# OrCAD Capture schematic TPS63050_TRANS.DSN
size D; title: TPS63050, Single Inductor Buck-Boost With 1-A Switches and; note: Datasheet: SLVSAM8D  EVM: SLVU806; note: Step-Down Converter.
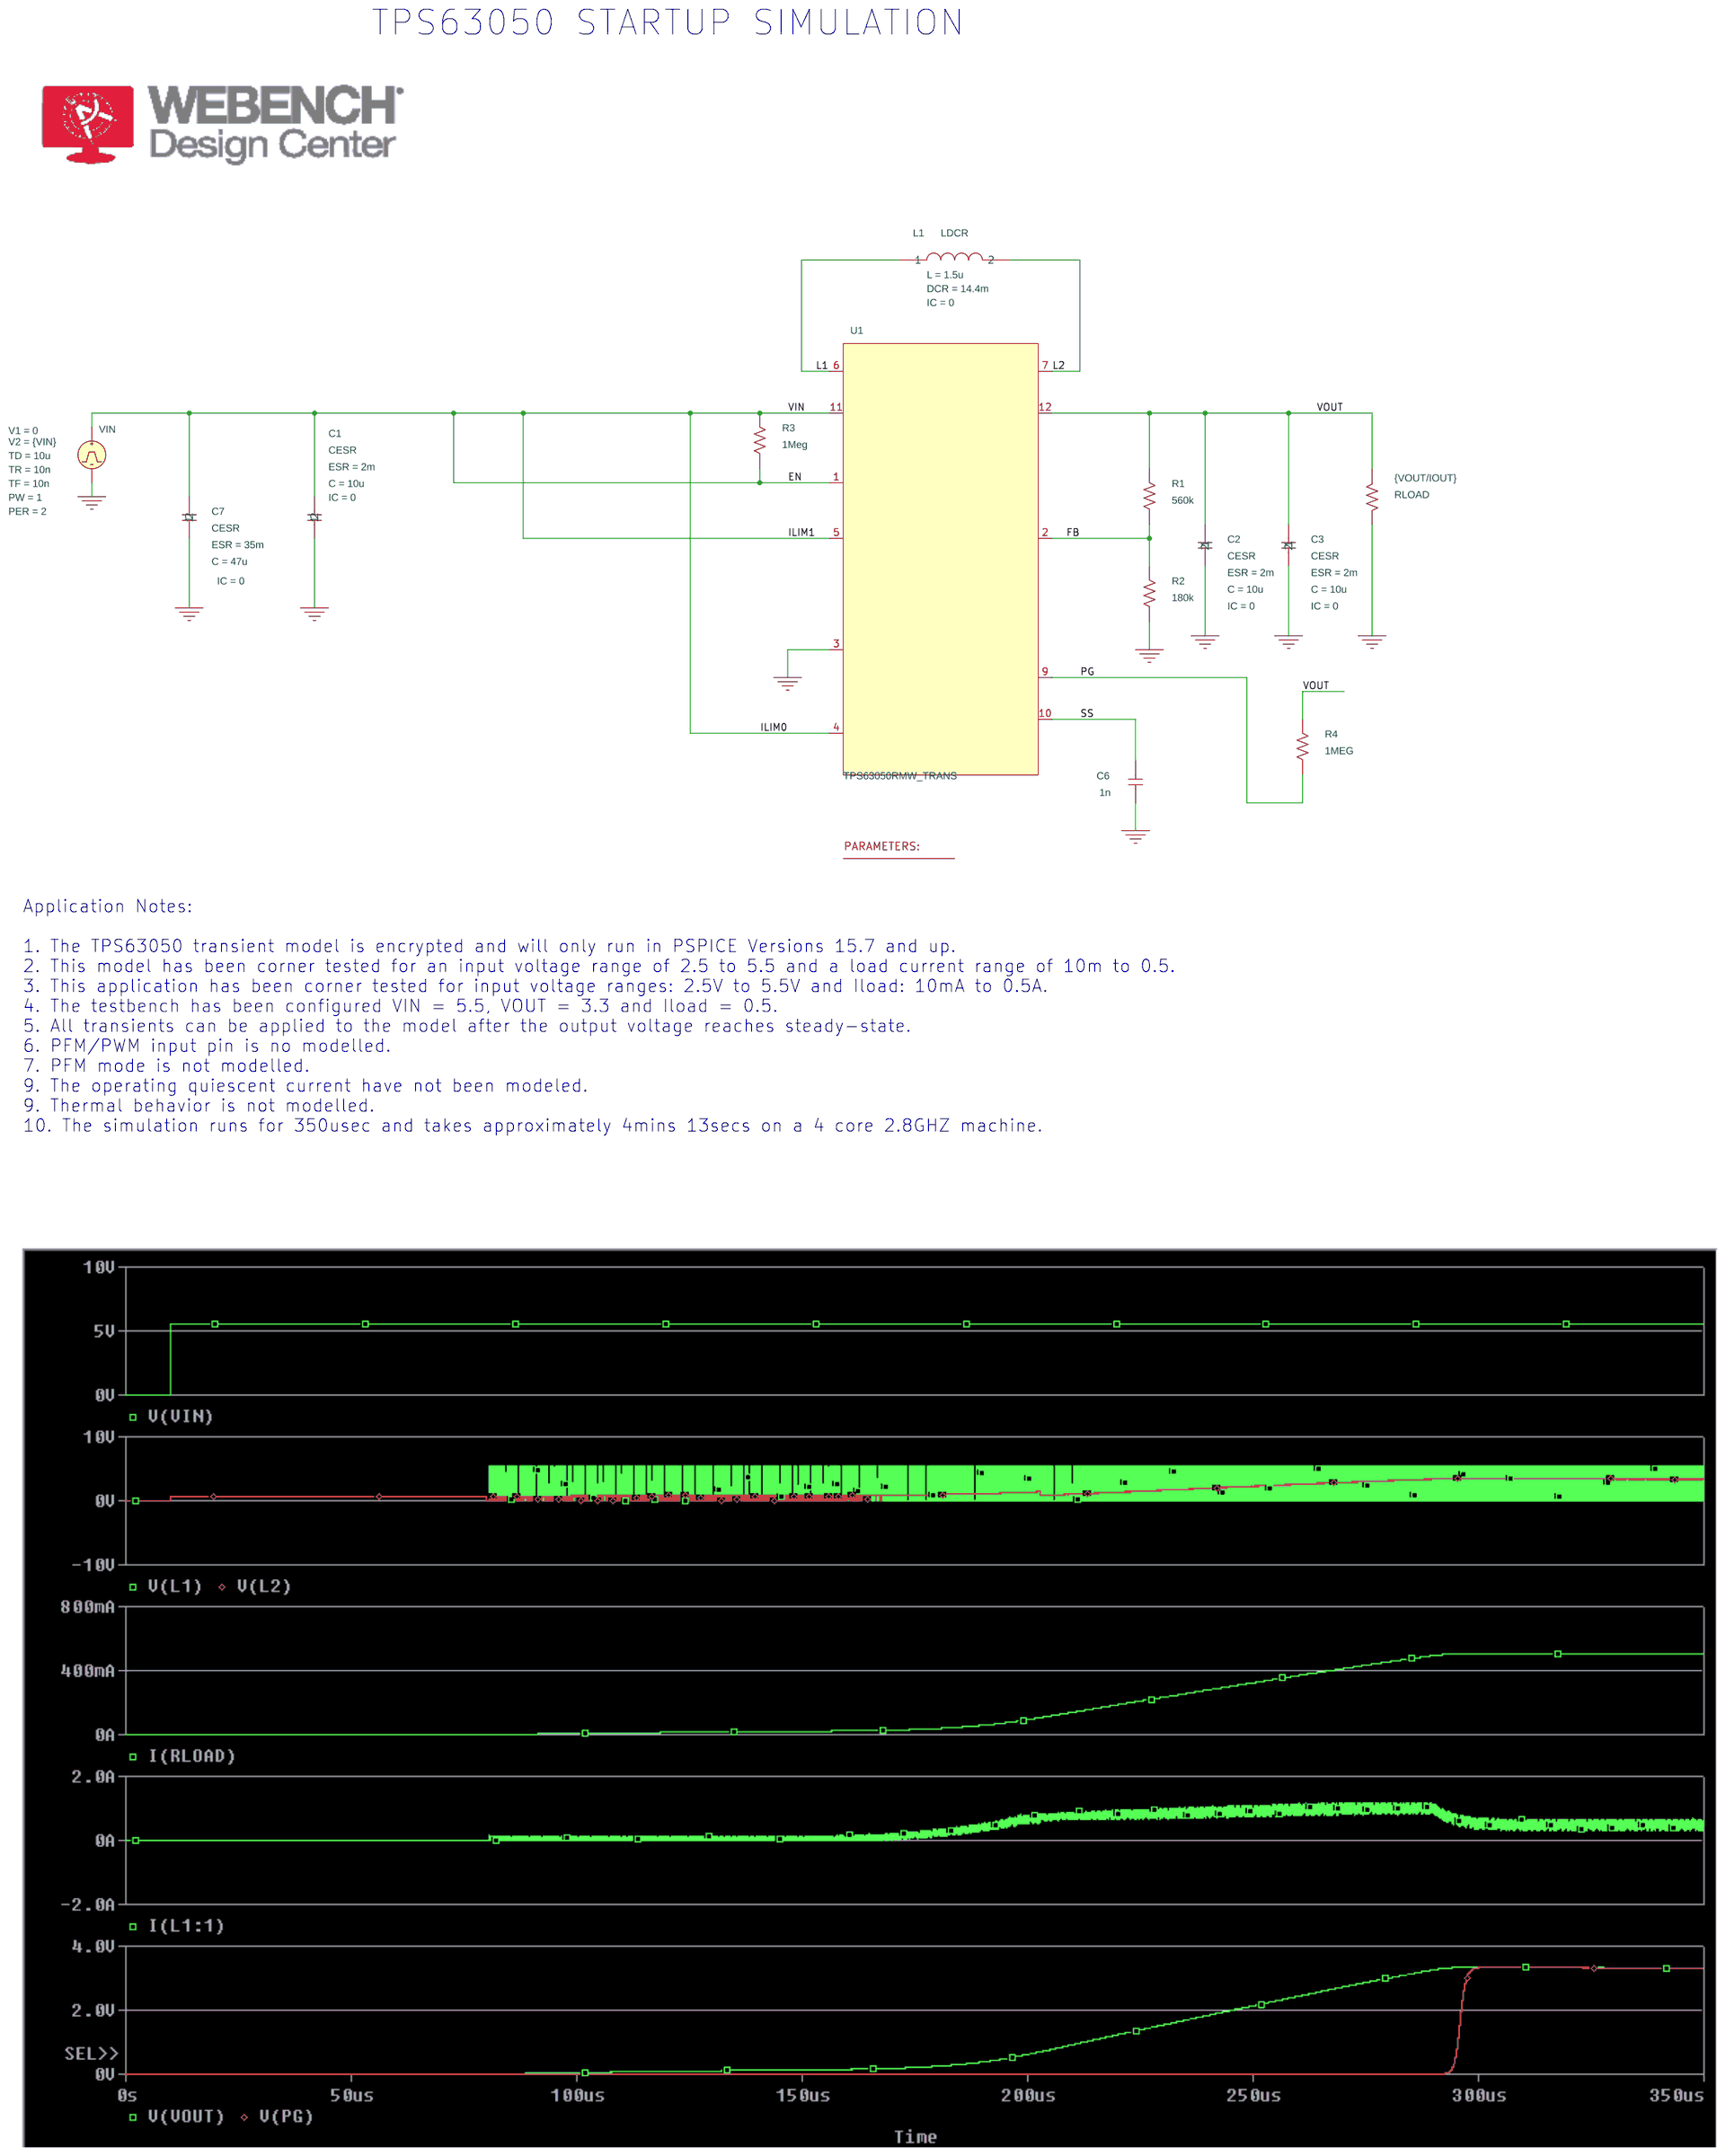
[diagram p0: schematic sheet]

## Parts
1  PARAM
C1  CESR
C2  CESR
C3  CESR
C6  1n  [RAD/CK05]
C7  CESR
L1  LDCR
R1  560k  [AX/RC05]
R2  180k  [AX/RC05]
R3  1Meg  [AX/RC05]
R4  1MEG  [AX/RC05]
RLOAD  {VOUT/IOUT}  [AX/RC05]
U1  TPS63050RMW_TRANS
VIN  VPULSE

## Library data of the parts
1 = PARAM: IOUT: 0.5; VIN: 5.5; VOUT: 3.3
C1 = CESR_0_2: C: 10u; ESR: 2m; IC: 0
C2 = CESR_0_1: C: 10u; ESR: 2m; IC: 0
C3 = CESR_0: C: 10u; ESR: 2m; IC: 0
C6 = C
C7 = CESR_0_3: C: 47u; ESR: 35m; IC: 0
L1 = LDCR_0: DCR: 14.4m; IC: 0; L: 1.5u
R1-R4 RLOAD = R
U1 = TPS63050RMW_TRANS
VIN = VPULSE: PER: 2; PW: 1; TD: 10u; TF: 10n; TR: 10n; V1: 0; V2: {VIN}

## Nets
0: C1.1 C2.2 C3.2 C6.1 C7.1 R2.1 RLOAD.2 U1.3(GND) VIN.2(-)
EN: C1.2 C7.2 R3.1 R3.2 U1.1(EN) U1.4(ILIM0) U1.5(ILIM1) U1.11(VIN) VIN.1(+)
FB: R1.1 R2.2 U1.2(FB)
L1: L1.1 U1.6(L1)
L2: L1.2 U1.7(L2)
PG: R4.1 U1.9(PG)
SS: C6.2 U1.10(SS)
VOUT: C2.1 C3.1 R1.2 R4.2 RLOAD.1 U1.12(VOUT)

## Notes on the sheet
- TPS63050 STARTUP SIMULATION
- Application Notes:
  1. The TPS63050 transient model is encrypted and will only run in PSPICE Versions 15.7 and up.
  2. This model has been corner tested for an input voltage range of 2.5 to 5.5 and a load current range of 10m to 0.5.
  3. This application has been corner tested for input voltage ranges: 2.5V to 5.5V and Iload: 10mA to 0.5A.
  4. The testbench has been configured VIN = 5.5, VOUT = 3.3 and Iload = 0.5.
  5. All transients can be applied to the model after the output voltage reaches steady-state.
  6. PFM/PWM input pin is no modelled.
  7. PFM mode is not modelled.
  9. The operating quiescent current have not been modeled.
  9. Thermal behavior is not modelled.
  10. The simulation runs for 350usec and takes approximately 4mins 13secs on a 4 core 2.8GHZ machine.
